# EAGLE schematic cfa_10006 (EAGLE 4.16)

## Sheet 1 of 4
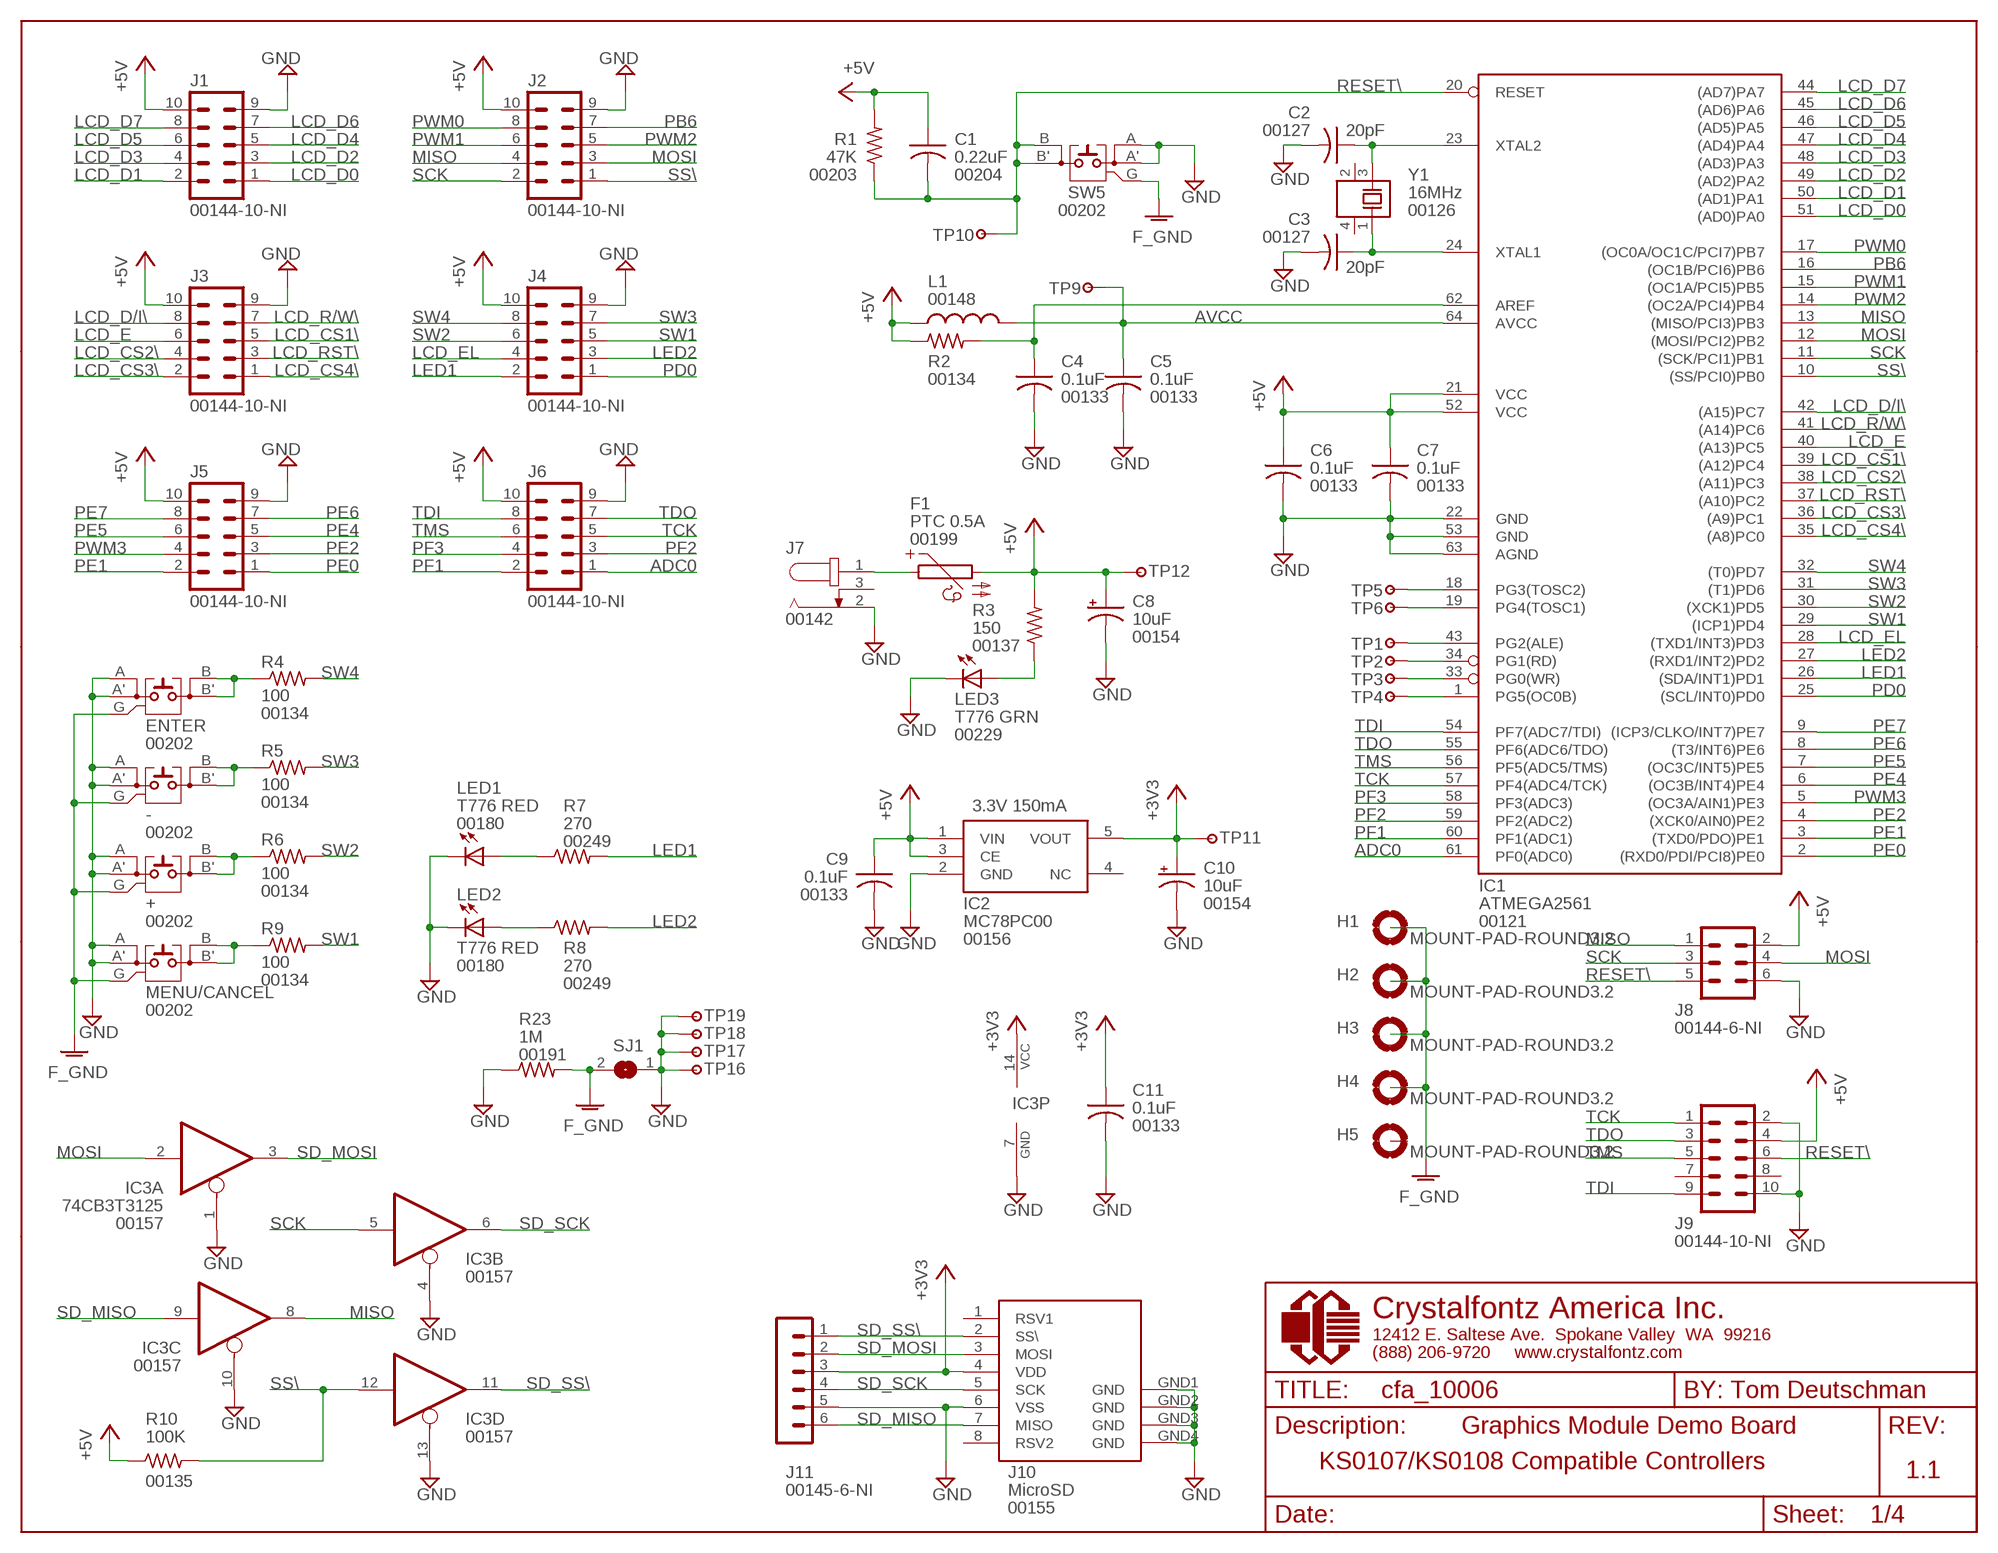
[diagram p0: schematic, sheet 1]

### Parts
+  00202  [EVQPB]
-  00202  [EVQPB]
C1  00204  [CAPC1608X90N]
C2  00127  [CAPC1608X87N]
C3  00127  [CAPC1608X87N]
C4  00133  [CAPC1608X87N]
C5  00133  [CAPC1608X87N]
C6  00133  [CAPC1608X87N]
C7  00133  [CAPC1608X87N]
C8  00154  [CAPMP6032X250N]
C9  00133  [CAPC1608X87N]
C10  00154  [CAPMP6032X250N]
C11  00133  [CAPC1608X87N]
ENTER  00202  [EVQPB]
F1  00199  [RESC3216X85N]
H1  MOUNT-PAD-ROUND3.2  [3,2-PAD]
H2  MOUNT-PAD-ROUND3.2  [3,2-PAD]
H3  MOUNT-PAD-ROUND3.2  [3,2-PAD]
H4  MOUNT-PAD-ROUND3.2  [3,2-PAD]
H5  MOUNT-PAD-ROUND3.2  [3,2-PAD]
IC1  00121  [TQFP64-AEB]
IC2  00156  [SOT23-5L]
IC3  00157  [TSSOP14]
J1  00144-10-NI  [MA05-2]
J2  00144-10-NI  [MA05-2]
J3  00144-10-NI  [MA05-2]
J4  00144-10-NI  [MA05-2]
J5  00144-10-NI  [MA05-2]
J6  00144-10-NI  [MA05-2]
J7  00142  [PJ-102AH]
J8  00144-6-NI  [MA03-2]
J9  00144-10-NI  [MA05-2]
J10  00155  [3M_MICROSD]
J11  00145-6-NI  [MA06-1]
L1  00148  [R0805]
LED1  00180  [T776_LED_BOTTOM]
LED2  00180  [T776_LED_BOTTOM]
LED3  00229  [T776_LED_BOTTOM]
MENU/CANCEL  00202  [EVQPB]
R1  00203  [RESC1608X50N]
R2  00134  [RESC1608X38N]
R3  00137  [R0603]
R4  00134  [RESC1608X38N]
R5  00134  [RESC1608X38N]
R6  00134  [RESC1608X38N]
R7  00249  00137  [R0603]
R8  00249  00137  [R0603]
R9  00134  [RESC1608X38N]
R10  00135  [RESC1608X38N]
R23  00191  [RESC1608X55N]
SJ1  SJ  [SJ]
SW5  00202  [EVQPB]
TP1  TP-VIA-3.2MM  [VIA-3.2MM-HOLE]
TP2  TP-VIA-3.2MM  [VIA-3.2MM-HOLE]
TP3  TP-VIA-3.2MM  [VIA-3.2MM-HOLE]
TP4  TP-VIA-3.2MM  [VIA-3.2MM-HOLE]
TP5  TP-VIA-3.2MM  [VIA-3.2MM-HOLE]
TP6  TP-VIA-3.2MM  [VIA-3.2MM-HOLE]
TP9  TP-VIA-1.0MM  [VIA-1MM-HOLE]
TP10  TP-VIA-1.0MM  [VIA-1MM-HOLE]
TP11  TP-VIA-1.0MM  [VIA-1MM-HOLE]
TP12  TP-VIA-1.0MM  [VIA-1MM-HOLE]
TP16  TP-VIA-1.0MM  [VIA-1MM-HOLE]
TP17  TP-VIA-1.0MM  [VIA-1MM-HOLE]
TP18  TP-VIA-1.0MM  [VIA-1MM-HOLE]
TP19  TP-VIA-1.0MM  [VIA-1MM-HOLE]
Y1  00126  [ECX-64]

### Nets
+3V3: C10.1(+) C11.1 IC2.5(VOUT) IC3.14(P:VCC) J10.4(VDD) J11.3 TP11.1
+5V: C1.1 C6.1 C7.1 C8.1(+) C9.1 F1.2 IC1.21(VCC) IC1.52(VCC) IC2.1(VIN) IC2.3(CE) J1.10 J2.10 J3.10 J4.10 J5.10 J6.10 J8.2 J9.4 L1.1 R1.2 R2.1 R3.2 R10.1 TP12.1 ; also sheet 3
ADC0: IC1.61(PF0(ADC0)) J6.1
AVCC: C5.1 IC1.64(AVCC) L1.2 TP9.1
FOO: +.A +.A' -.A -.A' C2.2 C3.2 C4.2 C5.2 C6.2 C7.2 C8.2(-) C9.2 C10.2(-) C11.2 ENTER.A ENTER.A' IC1.22(GND) IC1.53(GND) IC1.63(AGND) IC2.2(GND) IC3.1(A:OE) IC3.4(B:OE) IC3.7(P:GND) IC3.10(C:OE) IC3.13(D:OE) J1.9 J2.9 J3.9 J4.9 J5.9 J6.9 J7.2 J8.6 J9.2 J9.10 J10.6(VSS) J10.GND1(GND) J10.GND2(GND) J10.GND3(GND) J10.GND4(GND) J11.5 LED1.K(C) LED2.K(C) LED3.K(C) MENU/CANCEL.A MENU/CANCEL.A' R23.1 SJ1.1 SW5.A SW5.A' TP16.1 TP17.1 TP18.1 TP19.1 ; supply symbol labelled GND ; also sheet 2,3
GNDA: +.G -.G ENTER.G H1.B3,2(MOUNT) H2.B3,2(MOUNT) H3.B3,2(MOUNT) H4.B3,2(MOUNT) MENU/CANCEL.G R23.2 SJ1.2 SW5.G ; supply symbol labelled F_GND
LCD_CS1\: IC1.39((A12)PC4) J3.5 ; also sheet 2
LCD_CS2\: IC1.38((A11)PC3) J3.4 ; also sheet 2
LCD_CS3\: IC1.36((A9)PC1) J3.2 ; also sheet 2
LCD_CS4\: IC1.35((A8)PC0) J3.1
LCD_D0: IC1.51((AD0)PA0) J1.1 ; also sheet 2
LCD_D1: IC1.50((AD1)PA1) J1.2 ; also sheet 2
LCD_D2: IC1.49((AD2)PA2) J1.3 ; also sheet 2
LCD_D3: IC1.48((AD3)PA3) J1.4 ; also sheet 2
LCD_D4: IC1.47((AD4)PA4) J1.5 ; also sheet 2
LCD_D5: IC1.46((AD5)PA5) J1.6 ; also sheet 2
LCD_D6: IC1.45((AD6)PA6) J1.7 ; also sheet 2
LCD_D7: IC1.44((AD7)PA7) J1.8 ; also sheet 2
LCD_D/I\: IC1.42((A15)PC7) J3.8 ; also sheet 2
LCD_E: IC1.40((A13)PC5) J3.6 ; also sheet 2
LCD_EL: IC1.28((TXD1/INT3)PD3) J4.4 ; also sheet 2,3
LCD_R/W\: IC1.41((A14)PC6) J3.7 ; also sheet 2
LCD_RST\: IC1.37((A10)PC2) J3.3 ; also sheet 2
LED1: IC1.26((SDA/INT1)PD1) J4.2 R7.2
LED2: IC1.27((RXD1/INT2)PD2) J4.3 R8.2
MISO: IC1.13((MISO/PCI3)PB3) IC3.8(C:O) J2.4 J8.1
MOSI: IC1.12((MOSI/PCI2)PB2) IC3.2(A:I) J2.3 J8.4
N$1: C2.1 IC1.23(XTAL2) Y1.3
N$2: ENTER.B ENTER.B' R4.1
N$3: C3.1 IC1.24(XTAL1) Y1.1
N$4: -.B -.B' R5.1
N$5: IC1.19(PG4(TOSC1)) TP6.1
N$6: +.B +.B' R6.1
N$7: LED1.A R7.1
N$8: MENU/CANCEL.B MENU/CANCEL.B' R9.1
N$9: C4.1 IC1.62(AREF) R2.2
N$10: LED2.A R8.1
N$11: IC1.43(PG2(ALE)) TP1.1
N$13: IC1.34(PG1(RD)) TP2.1
N$14: F1.1 J7.1
N$15: IC1.33(PG0(WR)) TP3.1
N$16: IC1.1(PG5(OC0B)) TP4.1
N$17: LED3.A R3.1
N$18: IC1.18(PG3(TOSC2)) TP5.1
PB6: IC1.16((OC1B/PCI6)PB6) J2.7
PD0: IC1.25((SCL/INT0)PD0) J4.1
PE0: IC1.2((RXD0/PDI/PCI8)PE0) J5.1
PE1: IC1.3((TXD0/PDO)PE1) J5.2
PE2: IC1.4((XCK0/AIN0)PE2) J5.3
PE4: IC1.6((OC3B/INT4)PE4) J5.5
PE5: IC1.7((OC3C/INT5)PE5) J5.6
PE6: IC1.8((T3/INT6)PE6) J5.7
PE7: IC1.9((ICP3/CLKO/INT7)PE7) J5.8
PF1: IC1.60(PF1(ADC1)) J6.2
PF2: IC1.59(PF2(ADC2)) J6.3
PF3: IC1.58(PF3(ADC3)) J6.4
PWM0: IC1.17((OC0A/OC1C/PCI7)PB7) J2.8 ; also sheet 3
PWM1: IC1.15((OC1A/PCI5)PB5) J2.6 ; also sheet 3
PWM2: IC1.14((OC2A/PCI4)PB4) J2.5 ; also sheet 3
PWM3: IC1.5((OC3A/AIN1)PE3) J5.4 ; also sheet 3
RESET\: C1.2 IC1.20(RESET) J8.5 J9.6 R1.1 SW5.B SW5.B' TP10.1
SCK: IC1.11((SCK/PCI1)PB1) IC3.5(B:I) J2.2 J8.3
SD_MISO: IC3.9(C:I) J10.7(MISO) J11.6
SD_MOSI: IC3.3(A:O) J10.3(MOSI) J11.2
SD_SCK: IC3.6(B:O) J10.5(SCK) J11.4
SD_SS\: IC3.11(D:O) J10.2(SS\) J11.1
SS\: IC1.10((SS/PCI0)PB0) IC3.12(D:I) J2.1 R10.2
SW1: IC1.29((ICP1)PD4) J4.5 R9.2
SW2: IC1.30((XCK1)PD5) J4.6 R6.2
SW3: IC1.31((T1)PD6) J4.7 R5.2
SW4: IC1.32((T0)PD7) J4.8 R4.2
TCK: IC1.57(PF4(ADC4/TCK)) J6.5 J9.1
TDI: IC1.54(PF7(ADC7/TDI)) J6.8 J9.9
TDO: IC1.55(PF6(ADC6/TDO)) J6.7 J9.3
TMS: IC1.56(PF5(ADC5/TMS)) J6.6 J9.5
Unconnected: H5.B3,2(MOUNT) IC2.4(NC) J7.3 J9.7 J9.8 J10.1(RSV1) J10.8(RSV2) Y1.2 Y1.4

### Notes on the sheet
- 20pF
- 47K | 0.22uF
- 16MHz
- 20pF
- 0.1uF | 0.1uF
- 0.1uF | 0.1uF
- PTC 0.5A
- 10uF
- 150
- 100
- T776 GRN
- 100
- T776 RED | 3.3V 150mA
- 270
- 100 | 0.1uF
- 10uF
- ATMEGA2561
- MC78PC00
- T776 RED
- 100 | 270
- 1M
- 0.1uF
- 74CB3T3125
- Graphics Module Demo Board
- 100K
- KS0107/KS0108 Compatible Controllers
- 1.1
- MicroSD

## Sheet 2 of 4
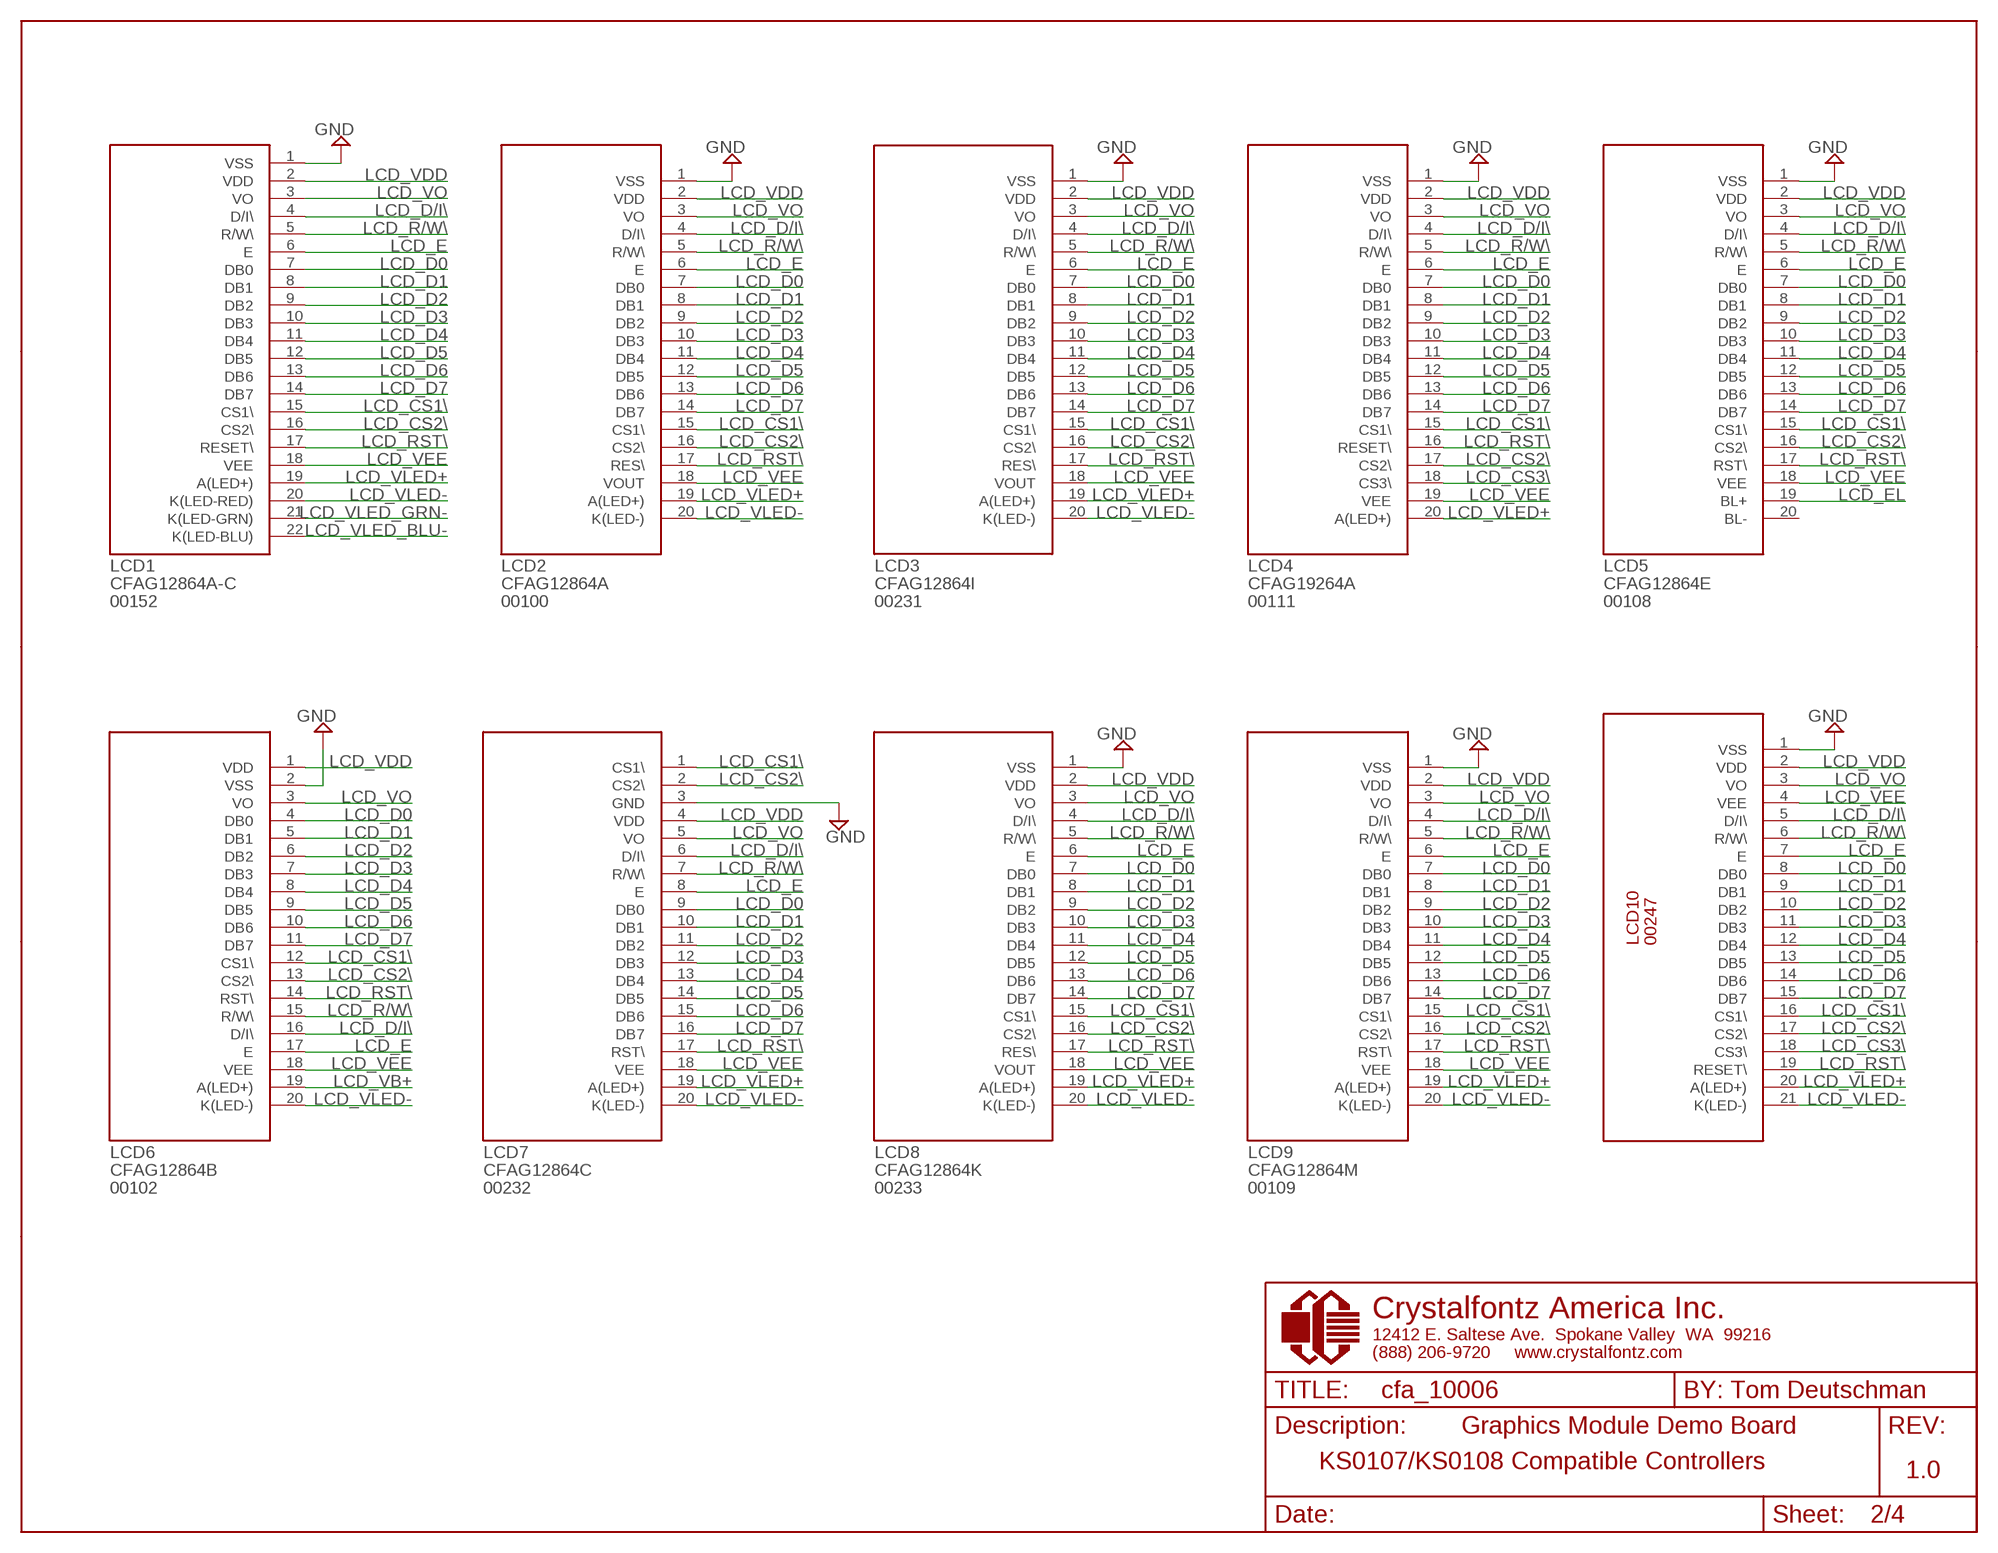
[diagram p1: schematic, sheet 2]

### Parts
LCD1  00152  [CFAG12864A-C-PLATED-HOLES]
LCD2  00100  [CFAG12864A-PLATED-HOLES]
LCD3  00231  [CFAG12864I-PLATED-HOLES]
LCD4  00111  [CFAG19264A-PLATED-HOLES]
LCD5  00108  [CFAG12864E-PLATED-HOLES]
LCD6  00102  [CFAG12864B-PLATED-HOLES]
LCD7  00232  [CFAG12864C-PLATED-HOLES]
LCD8  00233  [CFAG12864K-PLATED-HOLES]
LCD9  00109  [CFAG12864M-PLATED-HOLES]
LCD10  00247  [CFAG19264D-PLATED-HOLES]

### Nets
FOO: LCD1.1(VSS) LCD2.1(VSS) LCD3.1(VSS) LCD4.1(VSS) LCD5.1(VSS) LCD6.2(VSS) LCD7.3(GND) LCD8.1(VSS) LCD9.1(VSS) LCD10.1(VSS) ; supply symbol labelled GND ; also sheet 1,3
LCD_CS1\: LCD1.15(CS1\) LCD2.15(CS1\) LCD3.15(CS1\) LCD4.15(CS1\) LCD5.15(CS1\) LCD6.12(CS1\) LCD7.1(CS1\) LCD8.15(CS1\) LCD9.15(CS1\) LCD10.16(CS1\) ; also sheet 1
LCD_CS2\: LCD1.16(CS2\) LCD2.16(CS2\) LCD3.16(CS2\) LCD4.17(CS2\) LCD5.16(CS2\) LCD6.13(CS2\) LCD7.2(CS2\) LCD8.16(CS2\) LCD9.16(CS2\) LCD10.17(CS2\) ; also sheet 1
LCD_CS3\: LCD4.18(CS3\) LCD10.18(CS3\) ; also sheet 1
LCD_D0: LCD1.7(DB0) LCD2.7(DB0) LCD3.7(DB0) LCD4.7(DB0) LCD5.7(DB0) LCD6.4(DB0) LCD7.9(DB0) LCD8.7(DB0) LCD9.7(DB0) LCD10.8(DB0) ; also sheet 1
LCD_D1: LCD1.8(DB1) LCD2.8(DB1) LCD3.8(DB1) LCD4.8(DB1) LCD5.8(DB1) LCD6.5(DB1) LCD7.10(DB1) LCD8.8(DB1) LCD9.8(DB1) LCD10.9(DB1) ; also sheet 1
LCD_D2: LCD1.9(DB2) LCD2.9(DB2) LCD3.9(DB2) LCD4.9(DB2) LCD5.9(DB2) LCD6.6(DB2) LCD7.11(DB2) LCD8.9(DB2) LCD9.9(DB2) LCD10.10(DB2) ; also sheet 1
LCD_D3: LCD1.10(DB3) LCD2.10(DB3) LCD3.10(DB3) LCD4.10(DB3) LCD5.10(DB3) LCD6.7(DB3) LCD7.12(DB3) LCD8.10(DB3) LCD9.10(DB3) LCD10.11(DB3) ; also sheet 1
LCD_D4: LCD1.11(DB4) LCD2.11(DB4) LCD3.11(DB4) LCD4.11(DB4) LCD5.11(DB4) LCD6.8(DB4) LCD7.13(DB4) LCD8.11(DB4) LCD9.11(DB4) LCD10.12(DB4) ; also sheet 1
LCD_D5: LCD1.12(DB5) LCD2.12(DB5) LCD3.12(DB5) LCD4.12(DB5) LCD5.12(DB5) LCD6.9(DB5) LCD7.14(DB5) LCD8.12(DB5) LCD9.12(DB5) LCD10.13(DB5) ; also sheet 1
LCD_D6: LCD1.13(DB6) LCD2.13(DB6) LCD3.13(DB6) LCD4.13(DB6) LCD5.13(DB6) LCD6.10(DB6) LCD7.15(DB6) LCD8.13(DB6) LCD9.13(DB6) LCD10.14(DB6) ; also sheet 1
LCD_D7: LCD1.14(DB7) LCD2.14(DB7) LCD3.14(DB7) LCD4.14(DB7) LCD5.14(DB7) LCD6.11(DB7) LCD7.16(DB7) LCD8.14(DB7) LCD9.14(DB7) LCD10.15(DB7) ; also sheet 1
LCD_D/I\: LCD1.4(D/I\) LCD2.4(D/I\) LCD3.4(D/I\) LCD4.4(D/I\) LCD5.4(D/I\) LCD6.16(D/I\) LCD7.6(D/I\) LCD8.4(D/I\) LCD9.4(D/I\) LCD10.5(D/I\) ; also sheet 1
LCD_E: LCD1.6(E) LCD2.6(E) LCD3.6(E) LCD4.6(E) LCD5.6(E) LCD6.17(E) LCD7.8(E) LCD8.6(E) LCD9.6(E) LCD10.7(E) ; also sheet 1
LCD_EL: LCD5.19(BL+) ; also sheet 1,3
LCD_R/W\: LCD1.5(R/W\) LCD2.5(R/W\) LCD3.5(R/W\) LCD4.5(R/W\) LCD5.5(R/W\) LCD6.15(R/W\) LCD7.7(R/W\) LCD8.5(R/W\) LCD9.5(R/W\) LCD10.6(R/W\) ; also sheet 1
LCD_RST\: LCD1.17(RESET\) LCD2.17(RES\) LCD3.17(RES\) LCD4.16(RESET\) LCD5.17(RST\) LCD6.14(RST\) LCD7.17(RST\) LCD8.17(RES\) LCD9.17(RST\) LCD10.19(RESET\) ; also sheet 1
LCD_VB+: LCD6.19(A(LED+)) ; also sheet 3
LCD_VDD: LCD1.2(VDD) LCD2.2(VDD) LCD3.2(VDD) LCD4.2(VDD) LCD5.2(VDD) LCD6.1(VDD) LCD7.4(VDD) LCD8.2(VDD) LCD9.2(VDD) LCD10.2(VDD) ; also sheet 3
LCD_VEE: LCD1.18(VEE) LCD2.18(VOUT) LCD3.18(VOUT) LCD4.19(VEE) LCD5.18(VEE) LCD6.18(VEE) LCD7.18(VEE) LCD8.18(VOUT) LCD9.18(VEE) LCD10.4(VEE) ; also sheet 3
LCD_VLED+: LCD1.19(A(LED+)) LCD2.19(A(LED+)) LCD3.19(A(LED+)) LCD4.20(A(LED+)) LCD7.19(A(LED+)) LCD8.19(A(LED+)) LCD9.19(A(LED+)) LCD10.20(A(LED+)) ; also sheet 3
LCD_VLED-: LCD1.20(K(LED-RED)) LCD2.20(K(LED-)) LCD3.20(K(LED-)) LCD6.20(K(LED-)) LCD7.20(K(LED-)) LCD8.20(K(LED-)) LCD9.20(K(LED-)) LCD10.21(K(LED-)) ; also sheet 3
LCD_VLED_BLU-: LCD1.22(K(LED-BLU)) ; also sheet 3
LCD_VLED_GRN-: LCD1.21(K(LED-GRN)) ; also sheet 3
LCD_VO: LCD1.3(VO) LCD2.3(VO) LCD3.3(VO) LCD4.3(VO) LCD5.3(VO) LCD6.3(VO) LCD7.5(VO) LCD8.3(VO) LCD9.3(VO) LCD10.3(VO) ; also sheet 3
Unconnected: LCD5.20(BL-)

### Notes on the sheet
- CFAG12864A-C | CFAG12864A | CFAG12864I | CFAG19264A | CFAG12864E
- CFAG12864B | CFAG12864C | CFAG12864K | CFAG12864M
- Graphics Module Demo Board
- KS0107/KS0108 Compatible Controllers
- 1.0

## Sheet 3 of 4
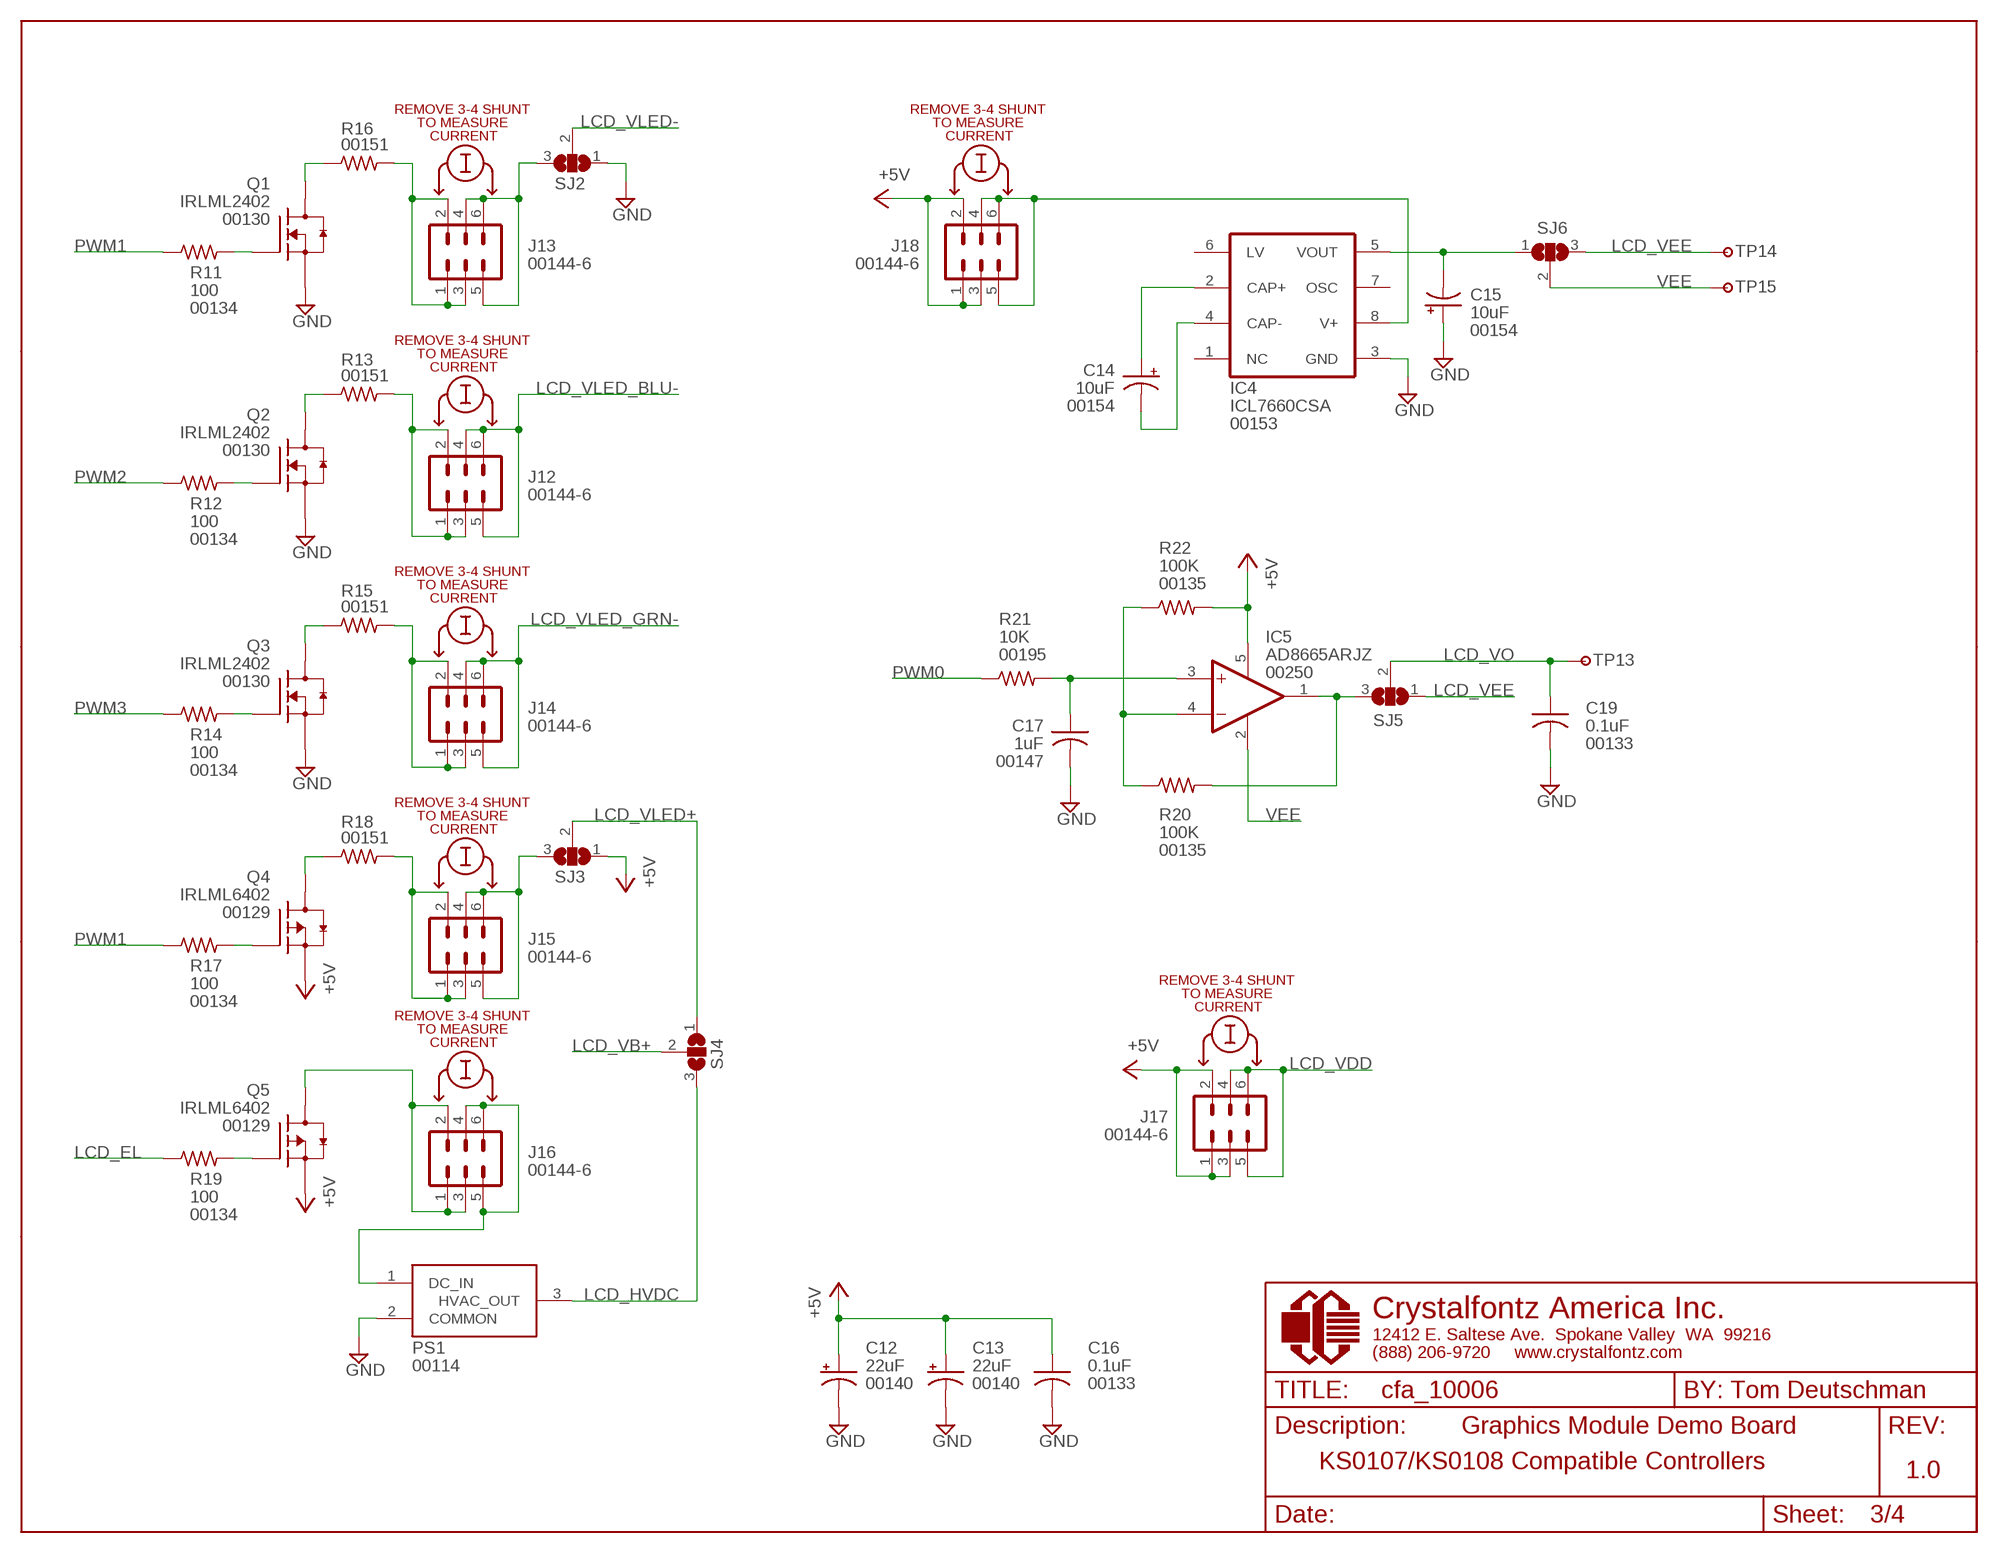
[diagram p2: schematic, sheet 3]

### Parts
C12  00140  [CAPMP3528X210N]
C13  00140  [CAPMP3528X210N]
C14  00154  [CAPMP6032X250N]
C15  00154  [CAPMP6032X250N]
C16  00133  [CAPC1608X87N]
C17  00147  [CAPC1608X87N]
C19  00133  [CAPC1608X87N]
IC4  00153  [SO08]
IC5  00250  00131  [SOT23-5L]
J12  00144-6  [MA03-2]
J13  00144-6  [MA03-2]
J14  00144-6  [MA03-2]
J15  00144-6  [MA03-2]
J16  00144-6  [MA03-2]
J17  00144-6  [MA03-2]
J18  00144-6  [MA03-2]
PS1  00114  [CFAIEL2]
Q1  00130  [SOT23]
Q2  00130  [SOT23]
Q3  00130  [SOT23]
Q4  00129  [SOT23]
Q5  00129  [SOT23]
R11  00134  [RESC1608X38N]
R12  00134  [RESC1608X38N]
R13  00151  [R2010]
R14  00134  [RESC1608X38N]
R15  00151  [R2010]
R16  00151  [R2010]
R17  00134  [RESC1608X38N]
R18  00151  [R2010]
R19  00134  [RESC1608X38N]
R20  00135  [RESC1608X38N]
R21  00195  00136  [R0603]
R22  00135  00177  [RESC1608X55N]
SJ2  SJ2W  [SJ_2]
SJ3  SJ2W  [SJ_2]
SJ4  SJ2W  [SJ_2]
SJ5  SJ2W  [SJ_2]
SJ6  SJ2W  [SJ_2]
TP13  TP-VIA-1.0MM  [VIA-1MM-HOLE]
TP14  TP-VIA-1.0MM  [VIA-1MM-HOLE]
TP15  TP-VIA-1.0MM  [VIA-1MM-HOLE]

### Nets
+5V: C12.1(+) C13.1(+) C16.1 IC5.5(VCC+) J17.1 J17.2 J17.3 J18.1 J18.2 J18.3 Q4.2(S) Q5.2(S) R22.2 SJ3.1 ; also sheet 1
FOO: C12.2(-) C13.2(-) C15.1(+) C16.2 C17.2 C19.2 IC4.3(GND) PS1.2(COMMON) Q1.2(S) Q2.2(S) Q3.2(S) SJ2.1 ; supply symbol labelled GND ; also sheet 1,2
LCD_EL: R19.1 ; also sheet 1,2
LCD_HVDC: PS1.3(HVAC_OUT) SJ4.3
LCD_VB+: SJ4.2 ; also sheet 2
LCD_VDD: J17.4 J17.5 J17.6 ; also sheet 2
LCD_VEE: SJ5.1 SJ6.3 TP14.1 ; also sheet 2
LCD_VLED+: SJ3.2 SJ4.1 ; also sheet 2
LCD_VLED-: SJ2.2 ; also sheet 2
LCD_VLED_BLU-: J12.4 J12.5 J12.6 ; also sheet 2
LCD_VLED_GRN-: J14.4 J14.5 J14.6 ; also sheet 2
LCD_VO: C19.1 SJ5.2 TP13.1 ; also sheet 2
N$21: J12.1 J12.2 J12.3 R13.2
N$23: Q2.3(D) R13.1
N$24: Q2.1(G) R12.2
N$25: J13.1 J13.2 J13.3 R16.2
N$26: J13.4 J13.5 J13.6 SJ2.3
N$27: J14.1 J14.2 J14.3 R15.2
N$28: IC4.8(V+) J18.4 J18.5 J18.6
N$29: Q3.3(D) R15.1
N$30: Q1.3(D) R16.1
N$31: Q1.1(G) R11.2
N$32: Q3.1(G) R14.2
N$33: J15.1 J15.2 J15.3 R18.2
N$34: J15.4 J15.5 J15.6 SJ3.3
N$35: Q4.3(D1) R18.1
N$36: Q4.1(G) R17.2
N$37: J16.1 J16.2 J16.3 Q5.3(D1)
N$38: J16.4 J16.5 J16.6 PS1.1(DC_IN)
N$39: C14.1(+) IC4.2(CAP+)
N$40: Q5.1(G) R19.2
N$41: C14.2(-) IC4.4(CAP-)
N$42: IC5.4(-IN) R20.1 R22.1
N$43: C15.2(-) IC4.5(VOUT) SJ6.1
N$44: IC5.1(OUT) R20.2 SJ5.3
N$45: C17.1 IC5.3(+IN) R21.2
PWM0: R21.1 ; also sheet 1
PWM1: R11.1 R17.1 ; also sheet 1
PWM2: R12.1 ; also sheet 1
PWM3: R14.1 ; also sheet 1
VEE: IC5.2(VCC-) SJ6.2 TP15.1
Unconnected: IC4.1(NC) IC4.6(LV) IC4.7(OSC)

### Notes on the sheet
- REMOVE 3-4 SHUNT | REMOVE 3-4 SHUNT
- TO MEASURE | TO MEASURE
- CURRENT | CURRENT
- IRLML2402
- 100
- 10uF
- REMOVE 3-4 SHUNT
- TO MEASURE
- CURRENT
- 10uF
- ICL7660CSA
- IRLML2402
- 100
- 100K
- REMOVE 3-4 SHUNT
- TO MEASURE
- CURRENT
- 10K
- AD8665ARJZ
- IRLML2402
- 0.1uF
- 1uF
- 100
- REMOVE 3-4 SHUNT
- TO MEASURE
- CURRENT
- 100K
- IRLML6402
- REMOVE 3-4 SHUNT
- 100
- TO MEASURE
- CURRENT
- REMOVE 3-4 SHUNT
- TO MEASURE
- CURRENT
- IRLML6402
- 100
- 22uF | 22uF | 0.1uF
- Graphics Module Demo Board
- KS0107/KS0108 Compatible Controllers
- 1.0

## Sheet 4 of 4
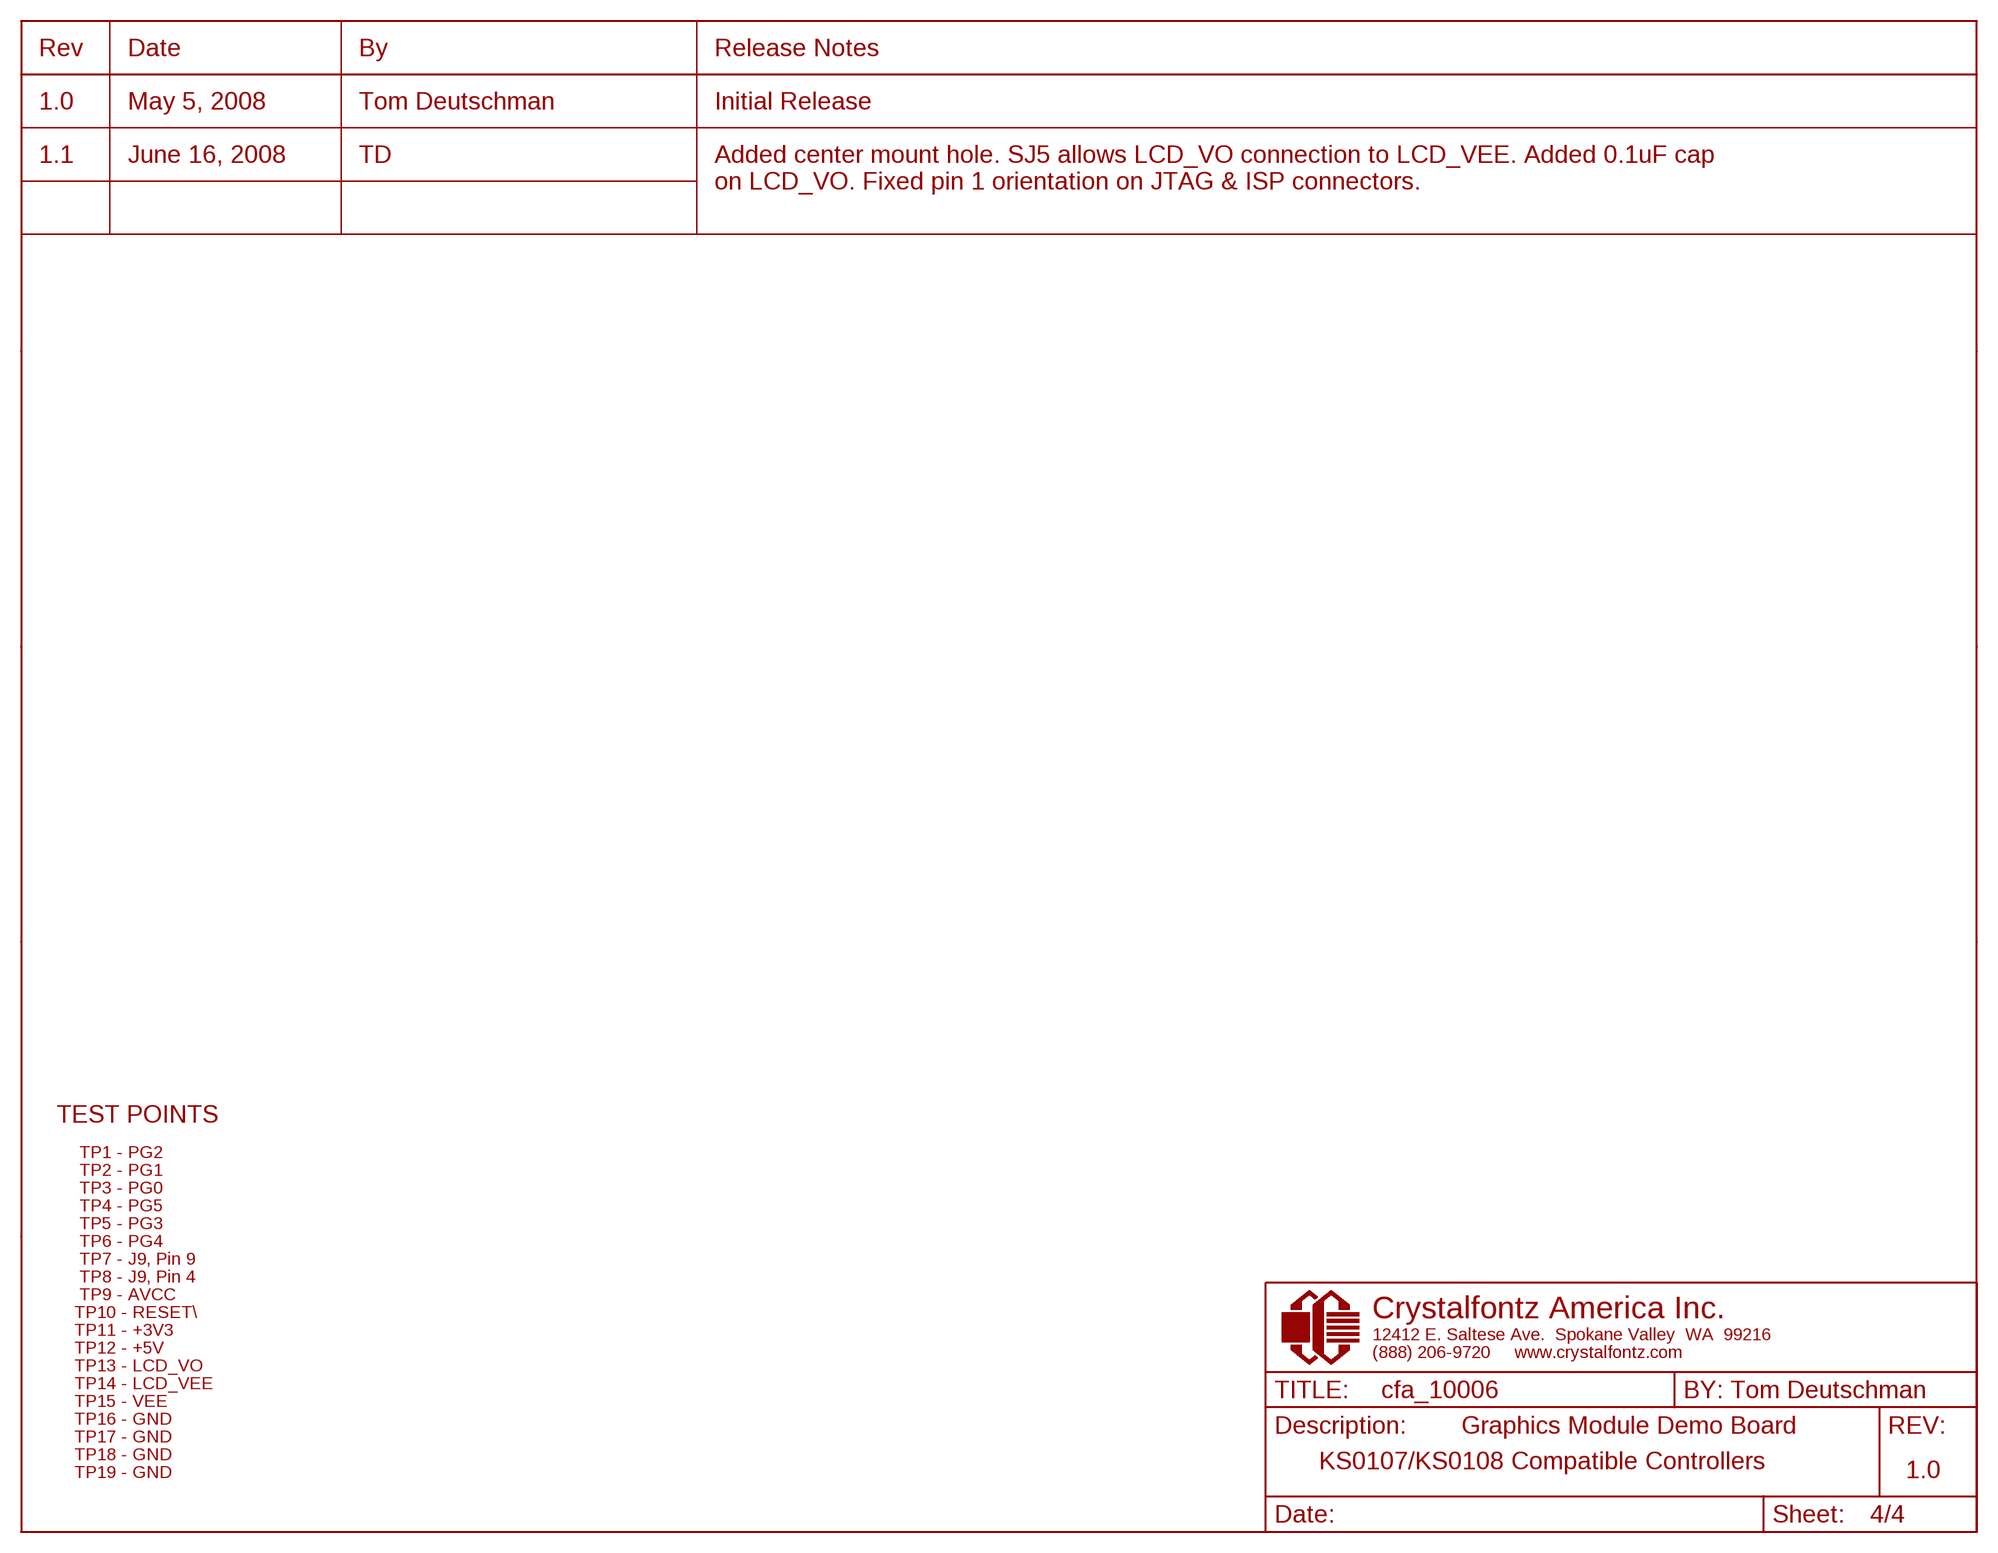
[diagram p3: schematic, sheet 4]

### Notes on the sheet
- Rev | Date | By | Release Notes
- 1.0 | May 5, 2008 | Tom Deutschman | Initial Release
- 1.1 | June 16, 2008 | TD | Added center mount hole. SJ5 allows LCD_VO connection to LCD_VEE. Added 0.1uF cap
- on LCD_VO. Fixed pin 1 orientation on JTAG & ISP connectors.
- TEST POINTS
- TP1 - PG2
- TP2 - PG1
- TP3 - PG0
- TP4 - PG5
- TP5 - PG3
- TP6 - PG4
- TP7 - J9, Pin 9
- TP8 - J9, Pin 4
- TP9 - AVCC
- TP10 - RESET\
- TP11 - +3V3
- TP12 - +5V
- TP13 - LCD_VO
- TP14 - LCD_VEE
- TP15 - VEE
- TP16 - GND
- Graphics Module Demo Board
- TP17 - GND
- TP18 - GND
- KS0107/KS0108 Compatible Controllers
- TP19 - GND | 1.0

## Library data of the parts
+ - ENTER MENU/CANCEL SW5 = proddev_lib:00202: SPST MOM W/GND, 6MM LIGHT TOUCH SW W/GND H=7 TH
C1 = proddev_lib:00204: 0.22uF 10V, CAP .22UF 10V CERAMIC X5R 0603
C2 C3 = proddev_lib:00127: 20pF, CAP CER 20PF 50V 5% C0G 0603
C4-C7 C9 C11 C16 C19 = proddev_lib:00133: 0.1uF 16V, CAP .1UF 16V CERAMIC X7R 0603
C8 C10 C14 C15 = proddev_lib:00154: 10uF 10V, CAP TANT 10UF 10V 10% LOESR SMD
C12 C13 = proddev_lib:00140: 22uF 10V, CAP TANT 22UF 10V 10% LOESR SMD
C17 = proddev_lib:00147: 1.0uF 10V, CAP CERAMIC 1UF 10V X5R 0603
F1 = proddev_lib:00199: 500mA, PTC RESETTABLE .50A 13.2V 1206
H1-H5 = holes:MOUNT-PAD-ROUND: MOUNTING PAD, round
IC1 = proddev_lib:00121: ATmega2561-16AU, IC AVR MCU 256K 16MHZ 64TQFP 256 Kbytes FLASH 8 Kbytes SRAM 4 Kbytes EEPROM DUAL USART 8-channel 10 bit ADC
IC2 = proddev_lib:00156: MC78PC33, IC REG LDO 150MA 3.3V LN SOT23-5
IC3 = proddev_lib:00157: SN74CB3T3125, IC 3.3V QUAD FET SWITCH 14TSSOP
IC4 = proddev_lib:00153: ICL7660CSA, IC VOLT CONV CMOS SW-CAP 8-SOIC
IC5 = proddev_lib:00131: TS321, IC OP AMP SINGLE LOW-PWR SOT23-5
J1-J6 J9 = proddev_lib:00144-10-NI: 2X5 HDR, CONN HDR BRKWAY .100 VERT
J7 = proddev_lib:00142: 2.1x5.5MM, CONN PWR JACK 2.1X5.5MM HIGH CUR
J8 = proddev_lib:00144-6-NI: 2X3 HDR, CONN HDR BRKWAY .100 VERT
J10 = proddev_lib:00155: MICROSD SOCKET, CONN EJECT MICROSD PUSH-PUSH SMD
J11 = proddev_lib:00145-6-NI: 1X6 HDR, CONN HDR BRKWAY .100 VERT
J12-J18 = proddev_lib:00144-6: 2X3 HDR, CONN HDR BRKWAY .100 VERT
L1 = proddev_lib:00148: 10uH, FERRITE CHIP 1000 OHM 200MA 0805
LCD1 = proddev_lib:00152: CFAG12864A-CFH-TN, 128x64 Red/Green/Blue
LCD2 = proddev_lib:00100: CFAG12864A-YYH-VN, 128x64 Yellow/Green STN, Positive, Transflective, LED Array Backlit LCD Module
LCD3 = proddev_lib:00231: CFAG12864I
LCD4 = proddev_lib:00111: CFAG19264-TMI-TN, 192x64 LCD Module
LCD5 = proddev_lib:00108: CFAG12864E-WGH-TN, 128x64 STN Positive, Gray, Transflective, White EL Backlit LCD Module with EL Inverter on board
LCD6 = proddev_lib:00102: CFAG12864B-TFH-V, 128x64 FSTN Positive, Transflective, Wide Temperature, White LED backlit LCD Module with Built-in Negative Voltage Generator
LCD7 = proddev_lib:00232: CFAG12864C
LCD8 = proddev_lib:00233: CFAG12864K
LCD9 = proddev_lib:00109: CFAG12864M-TMI-TN, 128x64 STN Blue, Negative, Transmissive, White LED Edge Backlit LCD Module
LCD10 = proddev_lib:00247: CFAG19264D
LED1 LED2 = proddev_lib:00180: LST776, LED SUP RED REV GULWNG 645NM SMD
LED3 = proddev_lib:00229: LED GRN, LED PURE GRN REV GLWNG 562NM SMD
PS1 = proddev_lib:00114: CFAIEL2, EL Inverter
Q1-Q3 = proddev_lib:00130: IRLML2402, MOSFET N-CH 20V 1.2A SOT-23
Q4 Q5 = proddev_lib:00129: IRLML6402, MOSFET P-CH 20V 3.7A SOT-23
R1 = proddev_lib:00203: 47K 1/10W 5%, RES 47K OHM 1/10W 5% 0603 SMD
R2 R4-R6 R9 R11 R12 R14 R17 R19 = proddev_lib:00134: 100, RES 100 OHM 1/10W 5% 0603 SMD
R3 R7 R8 = proddev_lib:00137: 150, RES 150 OHM 1/10W 5% 0603 SMD
R10 R20 = proddev_lib:00135: 100K, RES 100K OHM 1/10W 5% 0603 SMD
R13 R15 R16 R18 = proddev_lib:00151: R 1/2W 2010, BACKLIGHT RES 1/2W 2010 SMD
R21 = proddev_lib:00136: 1K, RES 1.0K OHM 1/10W 5% 0603 SMD
R22 = proddev_lib:00177: 31.6K 1/10W 1%, RES 31.6K OHM 1/10W 1% 0603 SMD
R23 = proddev_lib:00191: 1.0M 1/10W 1%, RES 1.00M OHM 1/10W 1% 0603 SMD
SJ1 = proddev_lib:SJ: SMD solder JUMPER
SJ2-SJ6 = proddev_lib:SJ2W: SMD solder JUMPER
TP1-TP6 = proddev_lib:TP-VIA-3.2MM: 3.2MM Hole Via TP
TP9-TP19 = proddev_lib:TP-VIA-1.0MM: TP 1MM HOLE
Y1 = proddev_lib:00126: 16MHz, CRYSTAL 16.000MHZ SMT 20PF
